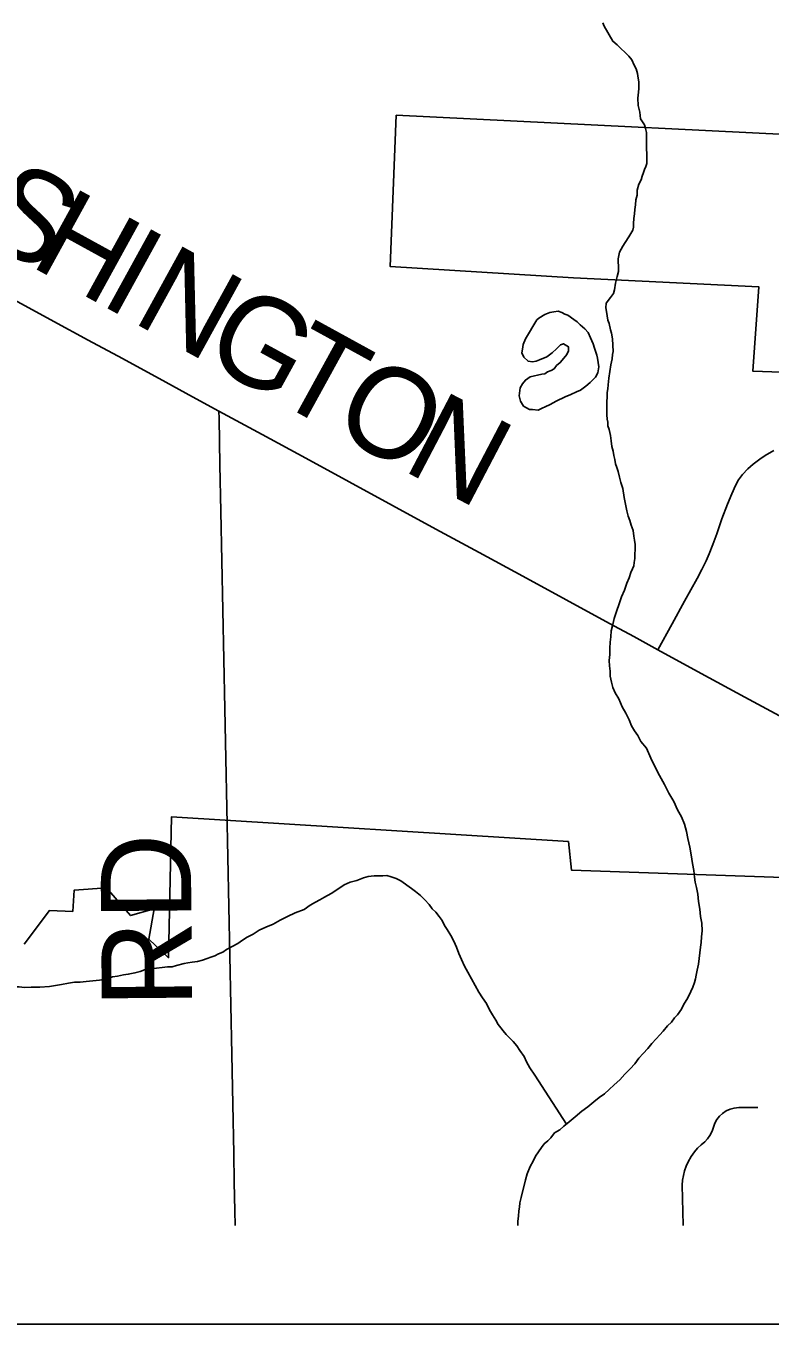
# Model space of a CAD drawing. Extents: x -11.4 to 84.1, y 11.1 to 59.
# Drawn here: x 27.387 to 27.855, y 40.548 to 41.365 of the extents above; entities that cross this region are included whole.
import ezdxf

# ---------------------------------------------------------------- set-up
doc = ezdxf.new("R2010")
doc.units = 0
for name, color, linetype in [('GM_X_Corporation', 7, 'Continuous'), ('GM_X_County_Road', 7, 'Continuous'), ('GM_X_County_Road_Text', 7, 'Continuous'), ('GM_X_Minor_Lake', 7, 'Continuous'), ('GM_X_Minor_River', 7, 'Continuous'), ('GM_X_Township_Road', 7, 'Continuous'), ('GM_X_Township_Road_Text', 7, 'Continuous'), ('SH_Data', 7, 'Continuous')]:
    doc.layers.add(name, color=color, linetype=linetype)

msp = doc.modelspace()

# ---------------------------------------------------------------- linework, layer by layer
at = {"layer": 'GM_X_Corporation'}
for points in [[(27.90359, 41.14549), (27.84377, 41.14758), (27.84748, 41.20059), (27.73085, 41.20635), (27.61568, 41.21337), (27.61954, 41.30861), (27.94083, 41.29266)], [(27.38559, 40.78722), (27.40144, 40.80833), (27.41605, 40.80785), (27.41694, 40.82108), (27.43721, 40.82261), (27.45241, 40.80521), (27.46733, 40.80952), (27.46397, 40.79036), (27.47637, 40.7787), (27.47818, 40.86721), (27.72771, 40.85174), (27.72962, 40.8338), (27.88101, 40.82851)]]:
    msp.add_lwpolyline(points, dxfattribs=at)
at = {"layer": 'GM_X_County_Road'}
for points in [[(27.37702, 41.19382), (27.4043, 41.17897), (27.42586, 41.16723), (27.44741, 41.1555)], [(27.44741, 41.1555), (27.4747, 41.14065), (27.49133, 41.13159), (27.50796, 41.12254), (27.53525, 41.10769), (27.56254, 41.09285), (27.58983, 41.07801), (27.61712, 41.06316), (27.64441, 41.04832), (27.6717, 41.03347), (27.69899, 41.01863), (27.72629, 41.00378), (27.75359, 40.98894), (27.76879, 40.98067), (27.784, 40.9724), (27.81128, 40.95754), (27.83857, 40.94268), (27.86585, 40.92782)]]:
    msp.add_lwpolyline(points, dxfattribs=at)
at = {"layer": 'GM_X_Minor_Lake'}
for points in [[(27.70782, 41.17998), (27.70919, 41.18098), (27.71295, 41.18332), (27.71597, 41.18451), (27.71862, 41.18493), (27.72127, 41.18536), (27.72356, 41.18463), (27.72548, 41.18352), (27.72739, 41.1828), (27.73123, 41.1802), (27.73316, 41.17871), (27.73509, 41.17684), (27.73817, 41.17423), (27.74011, 41.17198), (27.74168, 41.16858), (27.74248, 41.16669), (27.74327, 41.1648), (27.74407, 41.16216), (27.74567, 41.15762), (27.74608, 41.15572), (27.7465, 41.15307), (27.74693, 41.15041), (27.74623, 41.1466), (27.74476, 41.14392), (27.7414, 41.14044), (27.73878, 41.13811), (27.7354, 41.13577), (27.73276, 41.13459), (27.72937, 41.13302), (27.7256, 41.13143), (27.71995, 41.12868), (27.71618, 41.12671), (27.71317, 41.12514), (27.71128, 41.12435), (27.70865, 41.12317), (27.70522, 41.12349), (27.70332, 41.12346), (27.69949, 41.12568), (27.69754, 41.12869), (27.69672, 41.1321), (27.6974, 41.13705), (27.69887, 41.13974), (27.70073, 41.14205), (27.70374, 41.144), (27.71093, 41.14564), (27.71282, 41.14605), (27.7147, 41.14722), (27.71696, 41.14802), (27.71884, 41.14919), (27.72033, 41.15112), (27.72257, 41.15306), (27.72481, 41.15575), (27.72667, 41.15807), (27.72777, 41.16037), (27.72772, 41.16303), (27.72465, 41.16488), (27.72277, 41.16409), (27.72015, 41.16176), (27.71754, 41.15906), (27.71416, 41.15672), (27.70963, 41.15474), (27.70737, 41.15395), (27.7051, 41.15353), (27.70243, 41.15387), (27.69973, 41.15648), (27.69854, 41.15913), (27.69889, 41.16141), (27.69922, 41.16446), (27.70068, 41.16791), (27.70782, 41.17998)], [(27.70865, 41.12317), (27.71128, 41.12435), (27.71317, 41.12514), (27.71618, 41.12671), (27.71995, 41.12868), (27.7256, 41.13143), (27.72937, 41.13302), (27.73276, 41.13459), (27.7354, 41.13577), (27.73878, 41.13811), (27.7414, 41.14044), (27.74476, 41.14392), (27.74623, 41.1466), (27.74693, 41.15041), (27.7465, 41.15307), (27.74608, 41.15572), (27.74567, 41.15762), (27.74407, 41.16216), (27.74327, 41.1648), (27.74248, 41.16669), (27.74168, 41.16858), (27.74011, 41.17198), (27.73817, 41.17423), (27.73509, 41.17684), (27.73316, 41.17871), (27.73123, 41.1802), (27.72739, 41.1828), (27.72548, 41.18352), (27.72356, 41.18463), (27.72127, 41.18536), (27.71862, 41.18493), (27.71597, 41.18451), (27.71295, 41.18332), (27.70919, 41.18098), (27.70782, 41.17998)], [(27.70782, 41.17998), (27.70068, 41.16791), (27.69922, 41.16446), (27.69889, 41.16141), (27.69854, 41.15913), (27.69973, 41.15648), (27.70243, 41.15387), (27.7051, 41.15353), (27.70737, 41.15395), (27.70963, 41.15474), (27.71416, 41.15672), (27.71754, 41.15906), (27.72015, 41.16176), (27.72277, 41.16409), (27.72465, 41.16488), (27.72772, 41.16303), (27.72777, 41.16037), (27.72667, 41.15807), (27.72481, 41.15575), (27.72257, 41.15306), (27.72033, 41.15112), (27.71884, 41.14919), (27.71696, 41.14802), (27.7147, 41.14722), (27.71282, 41.14605), (27.71093, 41.14564), (27.70374, 41.144), (27.70073, 41.14205), (27.69887, 41.13974), (27.6974, 41.13705), (27.69672, 41.1321), (27.69754, 41.12869), (27.69949, 41.12568), (27.70332, 41.12346), (27.70522, 41.12349), (27.70865, 41.12317)]]:
    msp.add_lwpolyline(points, dxfattribs=at)
at = {"layer": 'GM_X_Minor_River'}
for points in [[(27.77151, 41.31471), (27.77143, 41.31927), (27.77175, 41.32308), (27.77209, 41.32537), (27.77205, 41.32765), (27.77202, 41.32955), (27.7716, 41.33182), (27.77117, 41.33486), (27.77036, 41.33788), (27.76918, 41.34015), (27.76761, 41.34354), (27.76567, 41.34579), (27.76336, 41.34804), (27.76065, 41.35065), (27.75833, 41.3529), (27.75564, 41.35513), (27.75016, 41.36455), (27.74937, 41.36682)], [(27.76587, 41.01763), (27.76695, 41.02108), (27.76805, 41.02337), (27.76878, 41.02529), (27.76913, 41.0272), (27.76946, 41.02986), (27.76942, 41.03214), (27.76974, 41.03595), (27.7697, 41.03861), (27.76927, 41.04127), (27.76885, 41.04392), (27.76841, 41.04734), (27.76721, 41.05074), (27.7664, 41.05377), (27.76522, 41.05641), (27.7644, 41.05982), (27.76357, 41.06399), (27.76274, 41.06816), (27.76189, 41.07385), (27.76068, 41.07763), (27.75987, 41.08104), (27.75905, 41.08445), (27.75825, 41.0871), (27.75745, 41.08937), (27.75702, 41.09202), (27.75622, 41.09467), (27.75579, 41.09732), (27.75498, 41.10035), (27.75455, 41.10377), (27.75411, 41.10718), (27.75329, 41.11097), (27.75249, 41.11324), (27.75245, 41.11552), (27.75204, 41.11742), (27.752, 41.12008), (27.75193, 41.12388), (27.75186, 41.12844), (27.75218, 41.13149), (27.75214, 41.13415), (27.75248, 41.13644), (27.75281, 41.1391), (27.75312, 41.14329), (27.75381, 41.14749), (27.7545, 41.15168), (27.7552, 41.15549), (27.75553, 41.15816), (27.75588, 41.16007), (27.75537, 41.16804), (27.75493, 41.17146), (27.75413, 41.17373), (27.75331, 41.17752), (27.75251, 41.17979), (27.75208, 41.18244), (27.75166, 41.18509), (27.75124, 41.18737), (27.75157, 41.19042), (27.75417, 41.19388), (27.75603, 41.19658), (27.75675, 41.19887), (27.75744, 41.20306), (27.7585, 41.20726), (27.75921, 41.21032), (27.75918, 41.21222), (27.75915, 41.21412), (27.75912, 41.21602), (27.75908, 41.2183), (27.75977, 41.22249), (27.76088, 41.22441), (27.76198, 41.22633), (27.76346, 41.22864), (27.76568, 41.2321), (27.76827, 41.23632), (27.76862, 41.23823), (27.76858, 41.24051), (27.76891, 41.24356), (27.76924, 41.24661), (27.76957, 41.24927), (27.7699, 41.25232), (27.77023, 41.25537), (27.77094, 41.25842), (27.77089, 41.26146), (27.77196, 41.26528), (27.77344, 41.26797), (27.77416, 41.27026), (27.77488, 41.27256), (27.77561, 41.27447), (27.77633, 41.27638), (27.77706, 41.2783), (27.77703, 41.2802), (27.777, 41.2821), (27.77696, 41.28438), (27.77691, 41.28742), (27.77685, 41.29084), (27.77679, 41.29426), (27.77674, 41.29768), (27.77631, 41.30034), (27.77551, 41.30261), (27.77434, 41.30449), (27.77317, 41.30637), (27.77272, 41.31055), (27.77151, 41.31471)], [(27.70372, 40.64738), (27.70556, 40.65083), (27.70703, 40.6539), (27.70888, 40.65659), (27.71074, 40.65928), (27.7126, 40.66159), (27.71484, 40.66353), (27.71671, 40.66546), (27.71894, 40.66854), (27.72232, 40.6705), (27.72494, 40.67283), (27.72832, 40.67554), (27.73206, 40.67865), (27.73618, 40.68214), (27.73993, 40.68486), (27.74368, 40.68796), (27.74705, 40.69068), (27.75043, 40.69302), (27.75342, 40.69573), (27.75641, 40.69882), (27.76016, 40.70192), (27.76314, 40.7054), (27.7665, 40.70887), (27.76948, 40.71196), (27.77208, 40.71543), (27.77469, 40.71852), (27.77768, 40.7216), (27.78029, 40.72469), (27.78289, 40.72777), (27.78513, 40.73009), (27.78737, 40.73241), (27.78997, 40.73588), (27.79259, 40.7382), (27.79445, 40.74089), (27.79631, 40.74283), (27.79891, 40.74629), (27.79964, 40.7482), (27.80075, 40.75012), (27.80223, 40.75243), (27.8037, 40.75511), (27.8048, 40.75742), (27.8059, 40.76009), (27.80698, 40.76315), (27.80771, 40.76545), (27.80805, 40.76774), (27.80876, 40.77079), (27.80945, 40.7746), (27.81079, 40.78527), (27.81112, 40.78832), (27.81144, 40.79175), (27.81176, 40.79556), (27.81168, 40.8005), (27.81085, 40.80467), (27.81039, 40.80922), (27.80955, 40.81415), (27.80909, 40.81871), (27.80826, 40.82288), (27.80744, 40.82629), (27.80701, 40.82932), (27.80657, 40.8335), (27.80573, 40.83805), (27.80488, 40.84336), (27.80404, 40.84829), (27.80281, 40.85359), (27.80197, 40.85814), (27.80076, 40.86268), (27.79878, 40.86721), (27.79643, 40.87174), (27.79406, 40.87702), (27.79093, 40.88229), (27.78818, 40.88757), (27.78505, 40.89322), (27.7823, 40.8985), (27.77955, 40.90416), (27.77678, 40.91058), (27.7733, 40.9147), (27.77133, 40.91848), (27.76938, 40.92149), (27.76743, 40.9245), (27.76585, 40.92827), (27.76388, 40.93242), (27.76154, 40.93657), (27.75955, 40.94148), (27.75721, 40.94524), (27.75564, 40.94864), (27.75482, 40.95205), (27.75399, 40.95584), (27.75394, 40.95888), (27.7535, 40.96229), (27.75345, 40.96572), (27.75376, 40.96952), (27.7537, 40.97333), (27.75402, 40.97713), (27.75434, 40.98056), (27.75465, 40.98437), (27.75573, 40.98819), (27.75643, 40.992), (27.76113, 41.00577), (27.76296, 41.00998), (27.76441, 41.01419), (27.76587, 41.01763)], [(27.72653, 40.6741), (27.70655, 40.70484), (27.70344, 40.70936), (27.70148, 40.71313), (27.6999, 40.71652), (27.69718, 40.72028), (27.69523, 40.72329), (27.69291, 40.72592), (27.69058, 40.72854), (27.68865, 40.73041), (27.68672, 40.73266), (27.68517, 40.73453), (27.68361, 40.73679), (27.68204, 40.73943), (27.68009, 40.74282), (27.67814, 40.74583), (27.67617, 40.74998), (27.67383, 40.75336), (27.67149, 40.75713), (27.66915, 40.76127), (27.6668, 40.76542), (27.66445, 40.76956), (27.66248, 40.77333), (27.66052, 40.77748), (27.65893, 40.78126), (27.65735, 40.78541), (27.65576, 40.78919), (27.6538, 40.79258), (27.65147, 40.79634), (27.6499, 40.79898), (27.64833, 40.802), (27.64639, 40.80463), (27.64444, 40.80726), (27.64213, 40.8095), (27.64018, 40.81213), (27.63747, 40.81513), (27.63477, 40.81774), (27.63169, 40.82036), (27.629, 40.82221), (27.62246, 40.82705), (27.6194, 40.82852), (27.61634, 40.82961), (27.61367, 40.83033), (27.61101, 40.83028), (27.60836, 40.83024), (27.6057, 40.8302), (27.60191, 40.82975), (27.59888, 40.82894), (27.59473, 40.82735), (27.59057, 40.82615), (27.5868, 40.82456), (27.58267, 40.82183), (27.57854, 40.8191), (27.5744, 40.81675), (27.57139, 40.81518), (27.56875, 40.81362), (27.56537, 40.81166), (27.56161, 40.80894), (27.55595, 40.80694), (27.55105, 40.80458), (27.54654, 40.80223), (27.54202, 40.79987), (27.53749, 40.79789), (27.53335, 40.79592), (27.52959, 40.79358), (27.52583, 40.79162), (27.52282, 40.78967), (27.51981, 40.78772), (27.51643, 40.78576), (27.51266, 40.7838), (27.51041, 40.78224), (27.50777, 40.78105), (27.50551, 40.77988), (27.50286, 40.77907), (27.5006, 40.77827), (27.49758, 40.77708), (27.49456, 40.77627), (27.49115, 40.77584), (27.4885, 40.77542), (27.48622, 40.775), (27.4813, 40.77377), (27.47866, 40.77297), (27.47562, 40.77292), (27.47221, 40.77249), (27.4688, 40.77205), (27.46235, 40.77156), (27.45858, 40.76998), (27.45518, 40.76916), (27.45101, 40.76833), (27.44798, 40.7679), (27.4442, 40.76708), (27.44117, 40.76665), (27.43777, 40.76545), (27.43284, 40.76461), (27.42867, 40.76416), (27.4245, 40.76371), (27.42071, 40.76327), (27.41729, 40.76322)], [(27.41729, 40.76322), (27.4135, 40.76277), (27.40896, 40.76194), (27.40139, 40.76067), (27.39532, 40.76019), (27.39, 40.76011), (27.38582, 40.76004), (27.3824, 40.76036), (27.3786, 40.7603), (27.37443, 40.75985), (27.36988, 40.75977), (27.36533, 40.75894), (27.36118, 40.75735), (27.35742, 40.75539), (27.35252, 40.75303), (27.34951, 40.75108), (27.34538, 40.74834), (27.34124, 40.74599), (27.33748, 40.74365), (27.3341, 40.7417), (27.33222, 40.74014), (27.33034, 40.73897), (27.33034, 40.73897)], [(27.69599, 40.61026), (27.69597, 40.61113), (27.69594, 40.61303), (27.69627, 40.61608), (27.69659, 40.6195), (27.69693, 40.62179), (27.69727, 40.62446), (27.69797, 40.62789), (27.70082, 40.63896), (27.7019, 40.64279), (27.70372, 40.64738)]]:
    msp.add_lwpolyline(points, dxfattribs=at)
at = {"layer": 'GM_X_Township_Road'}
for points in [[(27.51823, 40.61026), (27.51804, 40.61952), (27.51768, 40.63756), (27.51732, 40.6556), (27.5167, 40.68667), (27.51607, 40.71773), (27.51545, 40.74879), (27.51483, 40.77985), (27.51421, 40.81092), (27.51359, 40.84198), (27.51297, 40.87304), (27.51235, 40.9041), (27.51172, 40.93517), (27.5111, 40.96623), (27.51047, 40.99729), (27.50985, 41.02835), (27.50922, 41.05941), (27.50864, 41.08867), (27.50805, 41.11793), (27.50796, 41.12254)], [(27.784, 40.9724), (27.79294, 40.98866), (27.80081, 41.00296), (27.80868, 41.01727), (27.81157, 41.0229), (27.81426, 41.02833), (27.81618, 41.0327), (27.81863, 41.0386), (27.82107, 41.04538), (27.82424, 41.05474), (27.8277, 41.06396), (27.83042, 41.0704), (27.83289, 41.07578), (27.83476, 41.07924), (27.83722, 41.08255), (27.84053, 41.08616), (27.84399, 41.08918), (27.84802, 41.09235), (27.85148, 41.09452), (27.85696, 41.09783)], [(27.84684, 40.68455), (27.83495, 40.68446), (27.83192, 40.68415), (27.82936, 40.68344), (27.82699, 40.68237), (27.82457, 40.68073), (27.82268, 40.67893), (27.82111, 40.67685), (27.81983, 40.67455), (27.81893, 40.67201), (27.81803, 40.66958), (27.81666, 40.66696), (27.81513, 40.66486), (27.81343, 40.66294), (27.8112, 40.66099), (27.80898, 40.65887), (27.80698, 40.65657), (27.80485, 40.6536), (27.803, 40.6504), (27.80177, 40.64761), (27.80077, 40.64472), (27.80002, 40.64175), (27.79954, 40.63873), (27.7993, 40.63569), (27.79985, 40.61053), (27.79989, 40.61026)]]:
    msp.add_lwpolyline(points, dxfattribs=at)
at = {"layer": 'SH_Data'}
msp.add_line((26.16529, 40.54828), (33.16529, 40.54828), dxfattribs=at)

# ---------------------------------------------------------------- texts
at = {"layer": 'GM_X_County_Road_Text'}
for s, rotation, p in [('S', 331.22555, (27.35438, 41.23295)), ('H', 331.22528, (27.38798, 41.2145)), ('I', 331.22166, (27.43181, 41.19044)), ('N', 331.22827, (27.45226, 41.1792)), ('G', 331.22703, (27.49609, 41.15513)), ('T', 331.22591, (27.53992, 41.13106)), ('O', 331.28448, (27.57722, 41.11058)), ('N', 332.35686, (27.6221, 41.08601))]:
    msp.add_text(s, height=0.05682, rotation=rotation, dxfattribs=at).set_placement(p)
at = {"layer": 'GM_X_Township_Road_Text'}
msp.add_text('RD', height=0.056818, rotation=90.49555, dxfattribs=at).set_placement((27.4912, 40.74737))

doc.saveas('drawing.dxf')
